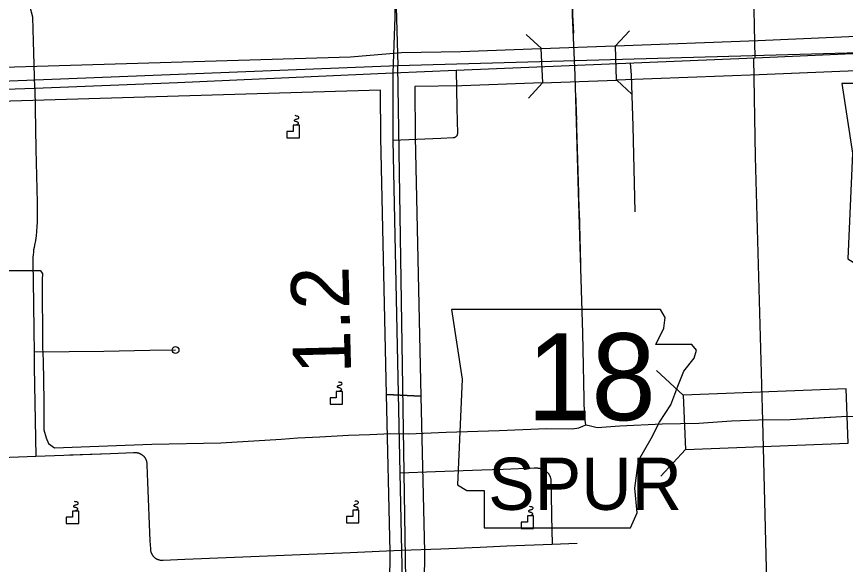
# Model space of a CAD drawing. Extents: x 646058 to 725608, y 1473014 to 1561048.
# Drawn here: x 653947 to 656968, y 1551144 to 1553140 of the extents above; entities that cross this region are included whole.
import ezdxf

# ---------------------------------------------------------------- set-up
doc = ezdxf.new("R2010")
doc.units = 0
doc.layers.add('Default', color=7, linetype='Continuous')

msp = doc.modelspace()

# ---------------------------------------------------------------- linework, layer by layer
at = {"layer": 'Default'}
for p, q in [((655862.1, 1552960.8), (655862.1, 1552960.8)), ((656132, 1552970.7), (656132, 1552970.7)), ((656376.9, 1551760.5), (656279.9, 1551850.1)), ((655295.8, 1551763.4), (655421, 1551757.2)), ((656384.7, 1551562.6), (656295.1, 1551465.7)), ((654474.1, 1551159.7), (654474, 1551159.7))]:
    msp.add_line(p, q, dxfattribs=at)
for points in [[(655261.9, 1555594.5), (655336.8, 1552961.3)], [(655262.6, 1555580.7), (655271, 1555315.3), (655283.1, 1554940.2), (655295.4, 1554506.4), (655308, 1553956.7), (655316.3, 1553613.4), (655324.8, 1553299), (655325.5, 1553138.1), (655318.4, 1552935.5)], [(655262.7, 1555576.5), (655271, 1555315.3), (655283.1, 1554940.2), (655295.4, 1554506.4), (655308, 1553956.7), (655316.3, 1553613.4), (655324.8, 1553299), (655325.5, 1553138.1), (655318.4, 1552935.5)], [(656022.1, 1551653.3), (656016.5, 1551688.2), (656011.1, 1551986.3), (655995, 1552500.7), (655983, 1552926.4), (655973.6, 1553146.6), (655964.2, 1553556.2), (655958.8, 1553599.2), (655921.2, 1553607.3), (655746.6, 1553601.9), (655505, 1553596.5), (655347.9, 1553593.9), (655247.2, 1553587.1), (654926.3, 1553576.4), (654515.4, 1553565.6), (654193.2, 1553554.9), (654002.5, 1553549.5)], [(654002.5, 1553549.5), (654193.2, 1553554.9), (654515.4, 1553565.6), (654926.3, 1553576.4), (655247.2, 1553587.1), (655347.9, 1553593.9), (655505, 1553596.5), (655746.6, 1553601.9), (655921.2, 1553607.3), (655958.8, 1553599.2), (655964.2, 1553556.2), (655973.6, 1553146.6), (655976.4, 1553079.7)], [(655970.5, 1553280.7), (655973.6, 1553146.6), (655976.3, 1553082.8)], [(656631.6, 1553280.3), (656638.2, 1552990.3)], [(654014, 1552879.7), (654008.2, 1553050.9), (654006.2, 1553137.5), (653995.8, 1553179)], [(654014, 1552879.7), (654008.2, 1553050.9), (654006.2, 1553137.5), (653995.8, 1553179)], [(655859.8, 1553023.2), (655804.9, 1553074.3)], [(656180.7, 1553088.1), (656129.7, 1553033.2)], [(656638.2, 1552990.3), (657627.2, 1553033.1), (657690.5, 1553039.9), (657774.3, 1553053.9), (657920.5, 1553086.9)], [(656638.2, 1552990.3), (657627.2, 1553033.1), (657690.5, 1553039.9), (657774.3, 1553053.9), (657920.5, 1553086.9)], [(656638.2, 1552990.3), (657627.2, 1553033.1), (657690.5, 1553039.9), (657774.3, 1553053.9), (657920.5, 1553086.9)], [(656638.2, 1552990.3), (657627.2, 1553033.1), (657690.5, 1553039.9), (657774.3, 1553053.9), (657920.5, 1553086.9)], [(652794.5, 1552922.9), (655163.6, 1552993.7), (655349.5, 1553009.3), (655566.8, 1553012.4), (655857.6, 1553023.2), (655864.5, 1552898.3), (655570.1, 1552887.5), (655398.6, 1552885), (655400, 1552700.4), (655421, 1551757.2), (655295.8, 1551763.4), (655275, 1552698.5), (655273.7, 1552871.9), (652860.9, 1552799.8)], [(655336.8, 1552961.3), (657922.4, 1553034.6)], [(655859.1, 1553023.2), (656127.3, 1553033.1)], [(655548.7, 1552945.2), (656638.2, 1552990.3)], [(655548.7, 1552945.2), (656638.2, 1552990.3)], [(655548.7, 1552945.2), (656638.2, 1552990.3)], [(655548.7, 1552945.2), (656638.2, 1552990.3)], [(656633.5, 1552988.2), (656639.2, 1552629.1), (656666.2, 1551666.9), (656680, 1551081.2), (656698.7, 1550359.8)], [(656633.5, 1552988.2), (656639.2, 1552629.1), (656666.2, 1551666.9), (656680, 1551081.2), (656698.7, 1550359.8)], [(652721.9, 1552858.1), (655336.8, 1552961.3)], [(655377.8, 1550308.6), (655336.8, 1552961.3)], [(656183.6, 1552971.5), (656187.4, 1552926.1), (656193.4, 1552740.8), (656200.1, 1552428.9)], [(654014, 1552879.7), (654533.2, 1552899.4), (655318.4, 1552935.5)], [(654014, 1552879.7), (654533.2, 1552899.4), (655318.4, 1552935.5)], [(654014, 1552879.7), (654533.2, 1552899.4), (655318.4, 1552935.5)], [(654014, 1552879.7), (654533.2, 1552899.4), (655318.4, 1552935.5)], [(655318.4, 1552935.5), (655317.9, 1552689)], [(655318.4, 1552935.5), (655317.9, 1552689)], [(655318.4, 1552935.5), (655317.9, 1552689)], [(655318.4, 1552935.5), (655317.9, 1552689)], [(655318.4, 1552935.5), (655548.7, 1552945.2)], [(655318.4, 1552935.5), (655548.7, 1552945.2)], [(655318.4, 1552935.5), (655548.7, 1552945.2)], [(655318.4, 1552935.5), (655548.7, 1552945.2)], [(655548.7, 1552945.2), (655552.1, 1552806.1), (655553.6, 1552714.4), (655553.6, 1552713.9), (655553.6, 1552713.3), (655553.6, 1552712.8), (655553.5, 1552712.3), (655553.5, 1552711.7), (655553.4, 1552711.2), (655553.3, 1552710.7), (655553.2, 1552710.1), (655553, 1552709.6), (655552.9, 1552709.1), (655552.7, 1552708.6), (655552.5, 1552708.1), (655552.3, 1552707.6), (655552.1, 1552707.1), (655551.8, 1552706.6), (655551.6, 1552706.1), (655551.3, 1552705.7), (655551, 1552705.2), (655550.7, 1552704.8), (655550.4, 1552704.3), (655550.1, 1552703.9), (655549.7, 1552703.5), (655549.3, 1552703.1)], [(655548.7, 1552945.2), (655552.1, 1552806.1), (655553.6, 1552714.4), (655553.6, 1552713.9), (655553.6, 1552713.3), (655553.6, 1552712.8), (655553.5, 1552712.3), (655553.5, 1552711.7), (655553.4, 1552711.2), (655553.3, 1552710.7), (655553.2, 1552710.1), (655553, 1552709.6), (655552.9, 1552709.1), (655552.7, 1552708.6), (655552.5, 1552708.1), (655552.3, 1552707.6), (655552.1, 1552707.1), (655551.8, 1552706.6), (655551.6, 1552706.1), (655551.3, 1552705.7), (655551, 1552705.2), (655550.7, 1552704.8), (655550.4, 1552704.3), (655550.1, 1552703.9), (655549.7, 1552703.5), (655549.3, 1552703.1)], [(655813.4, 1552843.4), (655864.5, 1552898.3)], [(655862.3, 1552898.3), (656133.6, 1552908.3)], [(656134.3, 1552908.3), (656189.2, 1552857.2)], [(653545, 1552863.1), (653553.7, 1552863.4), (653651.8, 1552866.9), (654014, 1552879.7)], [(653545, 1552863.1), (653553.7, 1552863.4), (653651.8, 1552866.9), (654014, 1552879.7)], [(653545, 1552863.1), (653553.7, 1552863.4), (653651.8, 1552866.9), (654014, 1552879.7)], [(653545, 1552863.1), (653553.7, 1552863.4), (653651.8, 1552866.9), (654014, 1552879.7)], [(654014, 1552879.7), (654017, 1552656.8), (654021.7, 1552462.3), (654022.1, 1552408.4), (654022, 1552391.5), (654021.3, 1552374.7), (654020, 1552357.8), (654018.2, 1552341), (654015.8, 1552324.3), (654012.2, 1552307), (654010.5, 1552298.4), (654009.2, 1552289.8), (654008.1, 1552281.2), (654007.2, 1552272.6), (654006.7, 1552263.9), (654006.4, 1552255.2), (654006.3, 1552246.5), (654006.6, 1552237.8), (654007.2, 1552178.3), (654009.7, 1552000.1), (654010.5, 1551913.1)], [(655984.8, 1552861.3), (656002.5, 1552237.4)], [(655984.8, 1552861.3), (655987.6, 1552762.4)], [(654967.2, 1552745), (654967.3, 1552745.3), (654967.4, 1552745.7), (654967.8, 1552746.1), (654968, 1552746.4), (654968.2, 1552746.6), (654968.6, 1552746.9), (654968.9, 1552747.1), (654969.2, 1552747.3), (654969.9, 1552747.6), (654970.4, 1552747.8), (654971, 1552748), (654971.9, 1552748.2), (654972.7, 1552748.6), (654973.8, 1552749.1), (654974.4, 1552749.9), (654974.9, 1552750.8), (654974.9, 1552751.9), (654974.4, 1552753), (654973.5, 1552754.3), (654971.5, 1552755.6), (654969.6, 1552756.5), (654967.2, 1552757.2), (654965.5, 1552757.6), (654964.3, 1552757.8), (654962.9, 1552758.1), (654961.2, 1552758.9), (654960.1, 1552760.1), (654959.9, 1552761.6), (654960.3, 1552763), (654961.2, 1552764.3), (654962.6, 1552765.4), (654964.3, 1552766.2), (654967, 1552766.9), (654969.3, 1552767.5), (654971.5, 1552767.9), (654973, 1552768.3), (654974.5, 1552769.3), (654975.8, 1552770.9), (654976.1, 1552772.6), (654976.1, 1552774.1), (654975.7, 1552775.2), (654973.8, 1552776.6), (654971, 1552777.3), (654969.3, 1552777.3), (654967.5, 1552777.5), (654964.8, 1552778.3), (654962.7, 1552779.2)], [(655549.3, 1552703.1), (655549, 1552702.7), (655548.6, 1552702.3), (655548.2, 1552702), (655547.8, 1552701.6), (655547.3, 1552701.3), (655546.9, 1552701), (655546.4, 1552700.7), (655546, 1552700.4), (655545.5, 1552700.1), (655545, 1552699.9), (655544.6, 1552699.6), (655544.1, 1552699.4), (655543.6, 1552699.2), (655543.1, 1552699), (655542.6, 1552698.8), (655542, 1552698.7), (655541.5, 1552698.6), (655541, 1552698.4), (655540.5, 1552698.3), (655539.9, 1552698.3), (655539.4, 1552698.2), (655538.8, 1552698.2), (655538.3, 1552698.1), (655493.4, 1552696), (655317.9, 1552689)], [(655549.3, 1552703.1), (655549, 1552702.7), (655548.6, 1552702.3), (655548.2, 1552702), (655547.8, 1552701.6), (655547.3, 1552701.3), (655546.9, 1552701), (655546.4, 1552700.7), (655546, 1552700.4), (655545.5, 1552700.1), (655545, 1552699.9), (655544.6, 1552699.6), (655544.1, 1552699.4), (655543.6, 1552699.2), (655543.1, 1552699), (655542.6, 1552698.8), (655542, 1552698.7), (655541.5, 1552698.6), (655541, 1552698.4), (655540.5, 1552698.3), (655539.9, 1552698.3), (655539.4, 1552698.2), (655538.8, 1552698.2), (655538.3, 1552698.1), (655493.4, 1552696), (655317.9, 1552689)], [(655317.9, 1552689), (655344.2, 1551477.5)], [(655317.9, 1552689), (655344.2, 1551477.5)], [(655317.9, 1552689), (655344.2, 1551477.5)], [(655317.9, 1552689), (655344.2, 1551477.5)], [(655989.5, 1552696.4), (655995.1, 1552498.5)], [(655997, 1552432.5), (656002.5, 1552237.4)], [(653396.5, 1552183.4), (653454.3, 1552180.3), (653604.3, 1552191.1), (653862.8, 1552215.3), (654033.4, 1552215.3), (654041.5, 1552203.6), (654040.6, 1552181.2), (654041.5, 1551936), (654043.3, 1551887.5), (654046, 1551739.4), (654046.9, 1551634.3), (654055, 1551605.6), (654063.9, 1551584.9), (654084.8, 1551569.1)], [(654010.5, 1551913.1), (654010.9, 1551862.3), (654017.2, 1551538.3)], [(654526.3, 1551925.3), (654432.6, 1551923.5), (654264.8, 1551919.8), (654012.5, 1551917)], [(655124.2, 1551775.1), (655124.4, 1551775.4), (655124.5, 1551775.8), (655124.8, 1551776.2), (655125.1, 1551776.5), (655125.3, 1551776.7), (655125.6, 1551777), (655125.9, 1551777.2), (655126.3, 1551777.4), (655126.9, 1551777.7), (655127.5, 1551777.9), (655128, 1551778.2), (655128.9, 1551778.4), (655129.8, 1551778.7), (655130.8, 1551779.2), (655131.5, 1551780), (655131.9, 1551780.9), (655132, 1551782), (655131.5, 1551783.1), (655130.6, 1551784.4), (655128.6, 1551785.7), (655126.7, 1551786.6), (655124.3, 1551787.4), (655122.6, 1551787.7), (655121.4, 1551787.9), (655120, 1551788.2), (655118.3, 1551789), (655117.2, 1551790.2), (655116.9, 1551791.7), (655117.3, 1551793.1), (655118.3, 1551794.4), (655119.6, 1551795.5), (655121.4, 1551796.3), (655124.1, 1551797), (655126.4, 1551797.6), (655128.6, 1551798), (655130.1, 1551798.4), (655131.6, 1551799.4), (655132.9, 1551801), (655133.2, 1551802.7), (655133.1, 1551804.2), (655132.7, 1551805.3), (655130.8, 1551806.7), (655128.1, 1551807.4), (655126.3, 1551807.5), (655124.6, 1551807.7), (655121.8, 1551808.4), (655119.8, 1551809.3)], [(655322.5, 1550511.2), (655306.6, 1550961.1), (655308.6, 1551189.5), (655295.8, 1551763.4)], [(655421, 1551757.2), (655433.6, 1551190.3), (655431.6, 1550962.7), (655447.4, 1550515.6)], [(656022.1, 1551653.3), (656033.8, 1551650.4), (656062.7, 1551643), (656146, 1551649.6), (656300.2, 1551656.2), (656433.9, 1551658.7), (656552.6, 1551666.9), (656650.8, 1551671), (656766.3, 1551672.7), (656953.5, 1551682.6), (657106.9, 1551686.7)], [(656811.3, 1551675.1), (656953.5, 1551682.6), (657106.9, 1551686.7)], [(656811.3, 1551675.1), (656910.1, 1551680.3)], [(654084.8, 1551569.1), (654440, 1551582.5), (654691.9, 1551587.7), (654911.8, 1551600.1), (654971.7, 1551605.2), (655052.2, 1551609.4), (655157.3, 1551615.2), (655234, 1551617.5), (655311.3, 1551620.9), (655376.1, 1551619.7), (655512.4, 1551626.6), (655705.6, 1551632.2), (655878.4, 1551639.1), (655973.8, 1551638.5), (655996, 1551641.3), (656011.3, 1551648.2), (656022.1, 1551653.3)], [(652730.8, 1551493.8), (653074.3, 1551504.6), (653575.9, 1551523.5), (653922.6, 1551534.8), (654017.1, 1551538.3)], [(654017.1, 1551538.3), (654289.8, 1551548.4), (654373.7, 1551551.5), (654374.9, 1551551.7), (654376.4, 1551551.8), (654377.9, 1551551.9), (654379.3, 1551551.9), (654380.8, 1551551.9), (654382.2, 1551551.8), (654383.7, 1551551.7), (654385.2, 1551551.5), (654386.6, 1551551.3), (654388, 1551551), (654389.5, 1551550.7), (654390.9, 1551550.3), (654392.3, 1551549.9), (654393.7, 1551549.4), (654395, 1551548.9), (654396.4, 1551548.3), (654397.7, 1551547.7), (654399, 1551547.1), (654400.3, 1551546.4), (654401.6, 1551545.6), (654402.8, 1551544.8), (654404, 1551544), (654405.2, 1551543.1), (654406.3, 1551542.2), (654407.4, 1551541.3), (654408.5, 1551540.3), (654409.6, 1551539.3), (654410.6, 1551538.2), (654411.6, 1551537.1), (654412.5, 1551536), (654413.4, 1551534.8), (654414.2, 1551533.6), (654415.1, 1551532.4), (654415.8, 1551531.2), (654416.5, 1551529.9), (654417.2, 1551528.6), (654417.9, 1551527.3), (654418.5, 1551525.9), (654419, 1551524.6), (654419.5, 1551523.2), (654420, 1551521.8), (654420.4, 1551520.4), (654420.7, 1551519), (654421, 1551517.5), (654421.3, 1551516.1), (654421.5, 1551514.6), (654421.6, 1551513.2), (654421.7, 1551511.7), (654421.8, 1551510.3), (654421.8, 1551508.8), (654421.7, 1551507.5), (654424.3, 1551443.5), (654432.7, 1551229.6), (654434.8, 1551200.6), (654434.9, 1551199), (654435, 1551197.6), (654435.1, 1551196.1), (654435.4, 1551194.7), (654435.6, 1551193.3), (654435.9, 1551191.9), (654436.3, 1551190.5), (654436.7, 1551189.1), (654437.2, 1551187.7), (654437.7, 1551186.4), (654438.2, 1551185), (654438.8, 1551183.7), (654439.5, 1551182.4), (654440.1, 1551181.1), (654440.9, 1551179.9), (654441.6, 1551178.7), (654442.4, 1551177.5), (654443.3, 1551176.3), (654444.2, 1551175.2), (654445.1, 1551174.1), (654446.1, 1551173), (654447.1, 1551172), (654448.1, 1551171), (654449.2, 1551170), (654450.3, 1551169.1), (654451.4, 1551168.2), (654452.6, 1551167.3), (654453.8, 1551166.5), (654455, 1551165.7), (654456.2, 1551165), (654457.5, 1551164.3), (654458.8, 1551163.7), (654460.1, 1551163.1), (654461.4, 1551162.5), (654462.8, 1551162), (654464.2, 1551161.6), (654465.5, 1551161.2), (654466.9, 1551160.8), (654468.3, 1551160.5), (654469.8, 1551160.2), (654471.2, 1551160), (654472.6, 1551159.8), (654474.1, 1551159.7)], [(654141.5, 1551542.9), (654289.8, 1551548.4), (654373.7, 1551551.5), (654374.9, 1551551.7), (654376.4, 1551551.8), (654377.9, 1551551.9), (654379.3, 1551551.9), (654380.8, 1551551.9), (654382.2, 1551551.8), (654383.7, 1551551.7), (654385.2, 1551551.5), (654386.6, 1551551.3), (654388, 1551551), (654389.5, 1551550.7), (654390.9, 1551550.3), (654392.3, 1551549.9), (654393.7, 1551549.4), (654395, 1551548.9), (654396.4, 1551548.3), (654397.7, 1551547.7), (654399, 1551547.1), (654400.3, 1551546.4), (654401.6, 1551545.6), (654402.8, 1551544.8), (654404, 1551544), (654405.2, 1551543.1), (654406.3, 1551542.2), (654407.4, 1551541.3), (654408.5, 1551540.3), (654409.6, 1551539.3), (654410.6, 1551538.2), (654411.6, 1551537.1), (654412.5, 1551536), (654413.4, 1551534.8), (654414.2, 1551533.6), (654415.1, 1551532.4), (654415.8, 1551531.2), (654416.5, 1551529.9), (654417.2, 1551528.6), (654417.9, 1551527.3), (654418.5, 1551525.9), (654419, 1551524.6), (654419.5, 1551523.2), (654420, 1551521.8), (654420.4, 1551520.4), (654420.7, 1551519), (654421, 1551517.5), (654421.3, 1551516.1), (654421.5, 1551514.6), (654421.6, 1551513.2), (654421.7, 1551511.7), (654421.8, 1551510.3), (654421.8, 1551508.8), (654421.7, 1551507.5), (654424.3, 1551443.5), (654432.7, 1551229.6), (654434.8, 1551200.6), (654434.9, 1551199), (654435, 1551197.6), (654435.1, 1551196.1), (654435.4, 1551194.7), (654435.6, 1551193.3), (654435.9, 1551191.9), (654436.3, 1551190.5), (654436.7, 1551189.1), (654437.2, 1551187.7), (654437.7, 1551186.4), (654438.2, 1551185), (654438.8, 1551183.7), (654439.5, 1551182.4), (654440.1, 1551181.1), (654440.9, 1551179.9), (654441.6, 1551178.7), (654442.4, 1551177.5), (654443.3, 1551176.3), (654444.2, 1551175.2), (654445.1, 1551174.1), (654446.1, 1551173), (654447.1, 1551172), (654448.1, 1551171), (654449.2, 1551170), (654450.3, 1551169.1), (654451.4, 1551168.2), (654452.6, 1551167.3), (654453.8, 1551166.5), (654455, 1551165.7), (654456.2, 1551165), (654457.5, 1551164.3), (654458.8, 1551163.7), (654460.1, 1551163.1), (654461.4, 1551162.5), (654462.8, 1551162), (654464.2, 1551161.6), (654465.5, 1551161.2), (654466.9, 1551160.8), (654468.3, 1551160.5), (654469.8, 1551160.2), (654471.2, 1551160), (654472.6, 1551159.8), (654474.1, 1551159.7)], [(655344.2, 1551477.5), (655474.3, 1551482.2), (655643.2, 1551488.6), (655720.8, 1551491.8), (655833, 1551496.2), (655835.5, 1551496.3), (655838, 1551496.3), (655840.4, 1551496.2), (655842.9, 1551496), (655845.3, 1551495.7), (655847.8, 1551495.3), (655850.2, 1551494.8), (655852.6, 1551494.3), (655855, 1551493.7), (655857.4, 1551492.9), (655859.7, 1551492.2), (655862, 1551491.3), (655864.3, 1551490.3), (655866.5, 1551489.3), (655868.7, 1551488.2), (655870.9, 1551487), (655873, 1551485.7), (655875.1, 1551484.4), (655877.1, 1551483), (655879.1, 1551481.5), (655881, 1551479.9), (655882.9, 1551478.3), (655884.7, 1551476.7), (655885.7, 1551475.3), (655886.7, 1551473.8), (655887.6, 1551472.4), (655888.5, 1551470.9), (655889.3, 1551469.4), (655890, 1551467.9), (655890.7, 1551466.3), (655891.4, 1551464.7), (655892, 1551463.1), (655892.5, 1551461.5), (655893, 1551459.9), (655893.5, 1551458.2), (655893.8, 1551456.5), (655894.2, 1551454.8), (655894.4, 1551453.1), (655894.6, 1551451.4), (655894.8, 1551449.7), (655894.9, 1551448), (655895.8, 1551400), (655897.2, 1551321.7), (655899.3, 1551218.1)], [(655344.2, 1551477.5), (655349.4, 1551192.5)], [(655344.2, 1551477.5), (655349.4, 1551192.5)], [(655344.2, 1551477.5), (655349.4, 1551192.5)], [(655344.2, 1551477.5), (655349.4, 1551192.5)], [(654162.4, 1551339.4), (654162.5, 1551339.7), (654162.6, 1551340.1), (654163, 1551340.5), (654163.2, 1551340.8), (654163.4, 1551341), (654163.8, 1551341.3), (654164.1, 1551341.5), (654164.4, 1551341.7), (654165.1, 1551342), (654165.6, 1551342.2), (654166.2, 1551342.4), (654167.1, 1551342.6), (654167.9, 1551343), (654169, 1551343.5), (654169.6, 1551344.3), (654170.1, 1551345.2), (654170.1, 1551346.3), (654169.6, 1551347.4), (654168.7, 1551348.7), (654166.7, 1551350), (654164.8, 1551350.9), (654162.4, 1551351.6), (654160.7, 1551352), (654159.5, 1551352.2), (654158.1, 1551352.5), (654156.4, 1551353.3), (654155.3, 1551354.5), (654155.1, 1551356), (654155.5, 1551357.4), (654156.4, 1551358.7), (654157.8, 1551359.8), (654159.5, 1551360.6), (654162.2, 1551361.3), (654164.5, 1551361.9), (654166.7, 1551362.3), (654168.2, 1551362.7), (654169.7, 1551363.7), (654171, 1551365.3), (654171.4, 1551367), (654171.3, 1551368.5), (654170.9, 1551369.6), (654169, 1551371), (654166.2, 1551371.7), (654164.5, 1551371.7), (654162.7, 1551371.9), (654160, 1551372.7), (654157.9, 1551373.6)], [(655184, 1551341.8), (655184.1, 1551342.2), (655184.3, 1551342.5), (655184.6, 1551342.9), (655184.9, 1551343.3), (655185.1, 1551343.5), (655185.4, 1551343.8), (655185.7, 1551344), (655186, 1551344.2), (655186.7, 1551344.5), (655187.3, 1551344.7), (655187.8, 1551344.9), (655188.7, 1551345.1), (655189.6, 1551345.5), (655190.6, 1551346), (655191.3, 1551346.8), (655191.7, 1551347.7), (655191.8, 1551348.8), (655191.3, 1551349.9), (655190.3, 1551351.2), (655188.3, 1551352.5), (655186.4, 1551353.4), (655184.1, 1551354.1), (655182.3, 1551354.5), (655181.1, 1551354.7), (655179.8, 1551354.9), (655178.1, 1551355.7), (655177, 1551357), (655176.7, 1551358.5), (655177.1, 1551359.9), (655178.1, 1551361.1), (655179.4, 1551362.3), (655181.1, 1551363), (655183.8, 1551363.8), (655186.2, 1551364.3), (655188.3, 1551364.7), (655189.8, 1551365.1), (655191.3, 1551366.2), (655192.6, 1551367.8), (655193, 1551369.4), (655192.9, 1551370.9), (655192.5, 1551372.1), (655190.6, 1551373.5), (655187.9, 1551374.1), (655186.1, 1551374.2), (655184.3, 1551374.4), (655181.6, 1551375.2), (655179.6, 1551376.1)], [(655820.6, 1551321.7), (655820.7, 1551322), (655820.9, 1551322.3), (655821.2, 1551322.7), (655821.5, 1551323.1), (655821.7, 1551323.3), (655822, 1551323.6), (655822.3, 1551323.8), (655822.7, 1551324), (655823.3, 1551324.3), (655823.9, 1551324.5), (655824.4, 1551324.7), (655825.3, 1551324.9), (655826.2, 1551325.3), (655827.2, 1551325.8), (655827.9, 1551326.6), (655828.3, 1551327.5), (655828.4, 1551328.6), (655827.9, 1551329.7), (655826.9, 1551331), (655825, 1551332.3), (655823.1, 1551333.2), (655820.7, 1551333.9), (655819, 1551334.3), (655817.8, 1551334.5), (655816.4, 1551334.7), (655814.7, 1551335.6), (655813.6, 1551336.8), (655813.3, 1551338.3), (655813.7, 1551339.7), (655814.7, 1551340.9), (655816, 1551342.1), (655817.8, 1551342.8), (655820.5, 1551343.6), (655822.8, 1551344.1), (655825, 1551344.6), (655826.5, 1551345), (655828, 1551346), (655829.3, 1551347.6), (655829.6, 1551349.3), (655829.5, 1551350.8), (655829.1, 1551351.9), (655827.2, 1551353.3), (655824.5, 1551354), (655822.7, 1551354), (655821, 1551354.2), (655818.2, 1551355), (655816.2, 1551355.9)], [(655349.2, 1551196.3), (655492.9, 1551201.1), (655637, 1551207.4)], [(655637, 1551207.4), (655733.9, 1551211.6), (655899.2, 1551218.1)], [(655899.2, 1551218.1), (655989.9, 1551221.2)], [(654474, 1551159.7), (654475.5, 1551159.7), (654476.9, 1551159.6), (654478.4, 1551159.7), (654479.8, 1551159.7), (654481.4, 1551159.9), (654559.8, 1551163.5), (654861.1, 1551175.5), (655163, 1551187.7), (655349.2, 1551196.3)], [(654474, 1551159.7), (654475.5, 1551159.7), (654476.9, 1551159.6), (654478.4, 1551159.7), (654479.8, 1551159.7), (654481.4, 1551159.9), (654559.8, 1551163.5), (654861.1, 1551175.5), (655163, 1551187.7), (655349.2, 1551196.3)], [(655349.4, 1551192.5), (655355.8, 1550939.9), (655369.4, 1550296.2)], [(655349.4, 1551192.5), (655355.8, 1550939.9), (655369.4, 1550296.2)], [(655349.4, 1551192.5), (655355.8, 1550939.9), (655369.4, 1550296.2)], [(655349.4, 1551192.5), (655355.8, 1550939.9), (655369.4, 1550296.2)]]:
    msp.add_lwpolyline(points, dxfattribs=at)
for points in [[(656129.7, 1553033.2), (656649.3, 1553052.3), (657701.2, 1553098.9), (657626.1, 1552968.4), (656654.3, 1552927.4), (656133.6, 1552908.3)], [(656955.2, 1552896.7), (656993.3, 1552643), (656976.4, 1552258.1), (657010.2, 1552236.9), (657073.7, 1552236.9), (657073.7, 1552101.6), (657606.6, 1552101.6), (657632, 1552156.6), (657623.5, 1552245.4), (657636.2, 1552346.9), (657682.7, 1552427.2), (657712.3, 1552486.5), (657754.6, 1552549.9), (657780, 1552617.6), (657801.1, 1552672.6), (657839.2, 1552719.1), (657847.7, 1552748.7), (657830.8, 1552769.8), (657699.6, 1552769.8), (657729.2, 1552829), (657733.5, 1552867.1), (657715.9, 1552896.3)], [(654932.3, 1552698.5), (654978.2, 1552698.5), (654978.2, 1552744.4), (654955.3, 1552744.4), (654955.3, 1552721.4), (654932.3, 1552721.4)], [(655532.8, 1552072.8), (655570.9, 1551819), (655554, 1551434.2), (655587.8, 1551413), (655651.3, 1551413), (655651.3, 1551277.7), (656184.2, 1551277.7), (656209.5, 1551332.7), (656201.1, 1551421.5), (656213.8, 1551523), (656260.3, 1551603.3), (656289.9, 1551662.6), (656332.2, 1551726), (656357.6, 1551793.7), (656378.7, 1551848.7), (656416.8, 1551895.2), (656425.3, 1551924.8), (656408.3, 1551945.9), (656277.2, 1551945.9), (656306.8, 1552005.1), (656311.1, 1552043.2), (656293.5, 1552072.4)], [(656384.7, 1551562.6), (656978.2, 1551586.1), (656970.4, 1551783.9), (656376.9, 1551760.5)], [(655089.4, 1551728.6), (655135.3, 1551728.6), (655135.3, 1551774.5), (655112.3, 1551774.5), (655112.3, 1551751.5), (655089.4, 1551751.5)], [(654127.5, 1551292.9), (654173.4, 1551292.9), (654173.4, 1551338.8), (654150.5, 1551338.8), (654150.5, 1551315.8), (654127.5, 1551315.8)], [(655149.1, 1551295.4), (655195, 1551295.4), (655195, 1551341.3), (655172.1, 1551341.3), (655172.1, 1551318.3), (655149.1, 1551318.3)], [(655785.8, 1551275.2), (655831.7, 1551275.2), (655831.7, 1551321.1), (655808.7, 1551321.1), (655808.7, 1551298.1), (655785.8, 1551298.1)]]:
    msp.add_lwpolyline(points, close=True, dxfattribs=at)
msp.add_circle((654526.3, 1551925.3), 12.5, dxfattribs=at)

# ---------------------------------------------------------------- texts
msp.add_text('1.2', height=211.2, rotation=91.473, dxfattribs=at).set_placement((655166.8, 1551840.3))
for s, height, p in [('18', 316.5, (655806.4, 1551669.7)), ('SPUR', 190.08, (655666, 1551343))]:
    msp.add_text(s, height=height, dxfattribs=at).set_placement(p)

doc.saveas('drawing.dxf')
